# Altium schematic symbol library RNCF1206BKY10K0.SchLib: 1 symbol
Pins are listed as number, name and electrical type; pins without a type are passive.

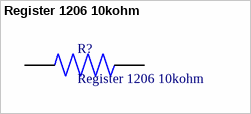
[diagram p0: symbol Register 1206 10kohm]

## Register 1206 10kohm
designator R?
MP: RNCF1206BKY10K0
footprint RESC3015X65N
pins: 1, 2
